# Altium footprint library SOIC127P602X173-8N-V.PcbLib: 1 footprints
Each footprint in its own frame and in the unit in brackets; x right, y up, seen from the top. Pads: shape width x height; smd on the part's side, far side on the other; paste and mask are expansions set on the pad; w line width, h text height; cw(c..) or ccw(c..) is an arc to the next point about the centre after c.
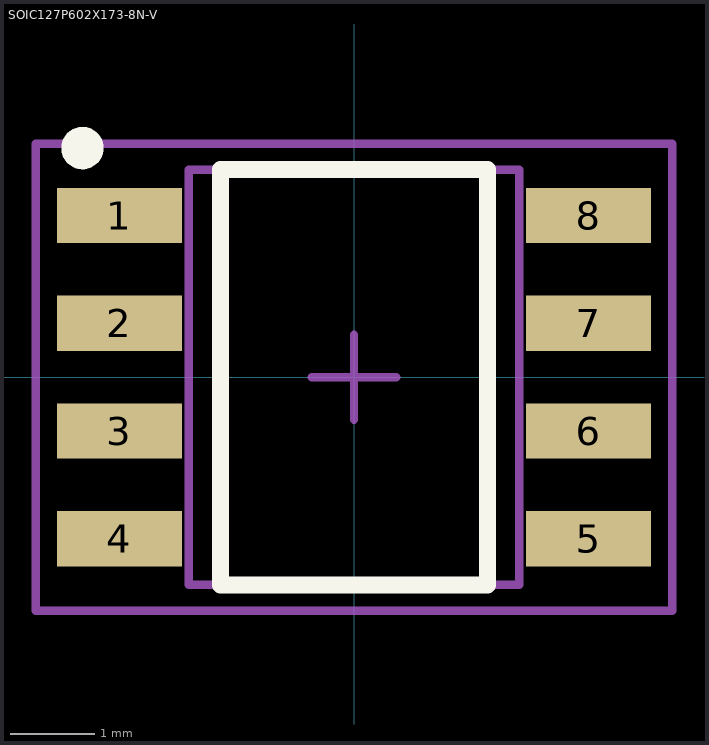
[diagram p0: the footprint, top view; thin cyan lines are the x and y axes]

## SOIC127P602X173-8N-V [mm] "SOIC,1.27mm pitch;8 pin,3.90mm W X 4.89mm L X 1.73mm H body"
height 1.73
pads (8):
  rect 1.47x0.65 smd paste+0 mask+0: 1(-2.765,1.905) 2(-2.765,0.635) 3(-2.765,-0.635) 4(-2.765,-1.905) 5(2.765,-1.905) 6(2.765,-0.635) 7(2.765,0.635) 8(2.765,1.905)
Top Overlay:
  circle w0.25: c-3.2,2.7 r0.125
  lines w0.2: -1.575,-2.45 1.575,-2.45 1.575,2.45 -1.575,2.45 -1.575,-2.45
M3 (ASY_Text_Top):
  text ".DESIGNATOR" at 0,0 h1.2
M13 (CMP_Body_OTL_Top):
  lines w0.1: -1.95,-2.445 1.95,-2.445 1.95,2.445 -1.95,2.445 -1.95,-2.445
M15 (CMP_Courtyard_Top):
  lines w0.1: -0.5,0 0.5,0 ; 0,-0.5 0,0.5 ; -3.75,-2.75 3.75,-2.75 3.75,2.75 -3.75,2.75 -3.75,-2.75
3D body "PG-DSO-8-60.stp": height 1.74, standoff 0, extent -3,-2.465 3,2.465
